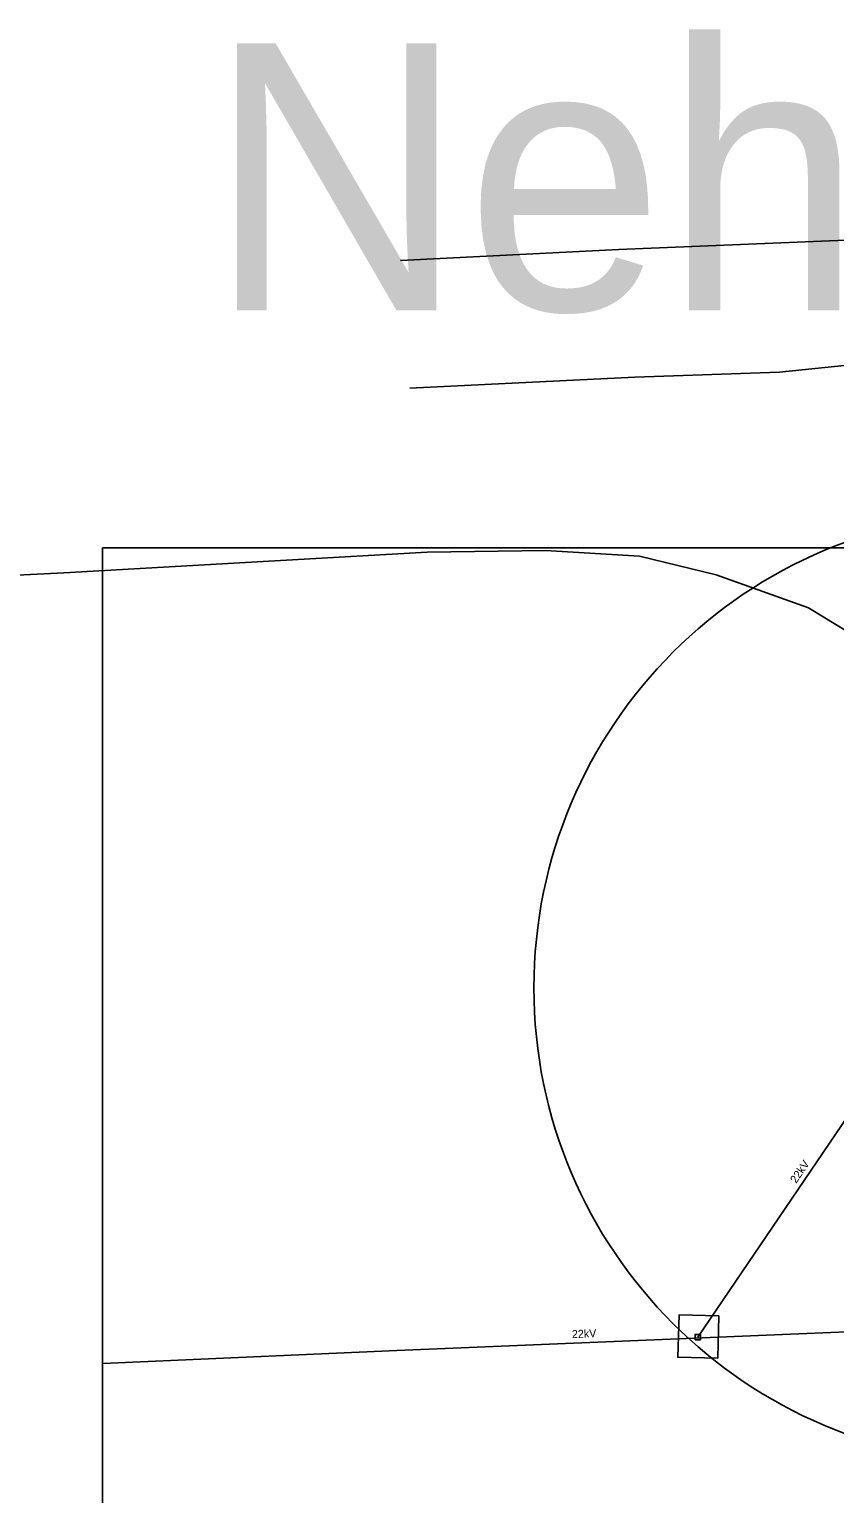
# Model space of a CAD drawing. Extents: x -726012 to -701762, y -1053295 to -1037771.
# Drawn here: x -721337.4 to -721307.2, y -1041950.3 to -1041895.5 of the extents above; entities that cross this region are included whole.
import ezdxf

# ---------------------------------------------------------------- set-up
doc = ezdxf.new("R2010")
doc.units = 0
for name, color, linetype in [('Level 3', 7, 'Continuous'), ('Vrstva 1', 7, 'Continuous'), ('Vrstva 23', 7, 'Continuous'), ('Vrstva 47', 7, 'Continuous'), ('Vrstva 61', 7, 'Continuous')]:
    doc.layers.add(name, color=color, linetype=linetype)

msp = doc.modelspace()

# ---------------------------------------------------------------- linework, layer by layer
at = {"layer": 'Level 3'}
msp.add_circle((-721300.703, -1041931.386), 17.788, dxfattribs=at)
at = {"layer": 'Vrstva 1'}
msp.add_lwpolyline([(-721306.35, -1041918.28), (-721308.21, -1041917.14), (-721311.66, -1041915.9), (-721314.53, -1041915.21), (-721318.06, -1041914.99), (-721322.49, -1041915.06), (-721336.1, -1041915.83), (-721349.81, -1041916.52), (-721356.26, -1041916.93), (-721363.81, -1041917.54), (-721375.89, -1041918.12), (-721387.4, -1041918.93), (-721393.03, -1041919.4), (-721401.39, -1041919.89), (-721405.96, -1041920.02), (-721425.23, -1041921.08), (-721439.72, -1041921.46), (-721450.44, -1041921.95)], dxfattribs=at)
at = {"layer": 'Vrstva 23'}
msp.add_line((-721311.602, -1041945.26), (-721311.57, -1041943.67), dxfattribs=at)
for points in [[(-721323.489, -1041904.129), (-721315.31, -1041903.71), (-721305.9, -1041903.32), (-721296.35, -1041902.94), (-721285.23, -1041902.47), (-721274.02, -1041901.83), (-721264.11, -1041901.32)], [(-721263.6, -1041907.34), (-721274.66, -1041907.95), (-721281.84, -1041908.5), (-721289.17, -1041908.27), (-721294.49, -1041907.59), (-721301.29, -1041908.02), (-721306.38, -1041908.01), (-721309.29, -1041908.31), (-721314.71, -1041908.5), (-721323.139, -1041908.913)], [(-721311.602, -1041945.26), (-721313.1, -1041945.23), (-721313.05, -1041943.64), (-721311.57, -1041943.67)]]:
    msp.add_lwpolyline(points, dxfattribs=at)
at = {"layer": 'Vrstva 47'}
for points in [[(-721312.353, -1041944.471), (-721305.78, -1041934.79), (-721304.957, -1041935.149)], [(-721334.645, -1041945.457), (-721323.63, -1041944.97), (-721301.95, -1041944.08), (-721295.85, -1041943.81), (-721213.36, -1041940.61), (-721168.645, -1041938.524)]]:
    msp.add_lwpolyline(points, dxfattribs=at)
at = {"layer": 'Vrstva 61'}
for points in [[(-721334.646, -1041914.888), (-721266.522, -1041914.888), (-721266.522, -1041992.986), (-721334.646, -1041992.986)], [(-721312.453, -1041944.571), (-721312.253, -1041944.571), (-721312.253, -1041944.371), (-721312.453, -1041944.371)]]:
    msp.add_lwpolyline(points, close=True, dxfattribs=at)

# ---------------------------------------------------------------- texts
at = {"layer": 'Vrstva 47'}
for rotation, p in [(55.818, (-721308.667, -1041938.732)), (2.3981, (-721317.061, -1041944.513))]:
    msp.add_text('22kV', height=0.3, rotation=rotation, dxfattribs=at).set_placement(p)
at = {"layer": 'Vrstva 61'}
msp.add_text('Nehvizdy', height=10, dxfattribs=at).set_placement((-721330.708, -1041905.993))

doc.saveas('drawing.dxf')
